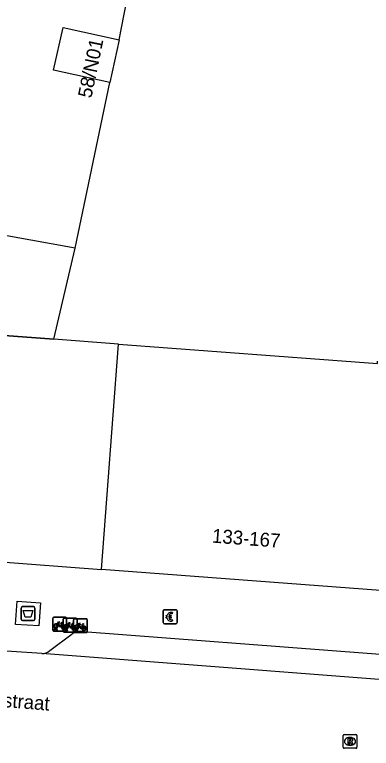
# Model space of a CAD drawing. Extents: x 160861 to 161308, y 384024 to 384878.
# Drawn here: x 161140.4 to 161166, y 384029.8 to 384082.5 of the extents above; entities that cross this region are included whole.
import ezdxf

# ---------------------------------------------------------------- set-up
doc = ezdxf.new("R2010")
doc.units = 0
for name, color, linetype in [('IMGEO_Afval_apart_plaats', 7, 'Continuous'), ('IMGEO_Betaalautomaat', 7, 'Continuous'), ('IMGEO_Fietsenrek', 7, 'Continuous'), ('IMGEO_Openbare_ruimte_label', 7, 'Continuous'), ('IMGEO_Pand', 7, 'Continuous'), ('IMGEO_Pand_nummerreeks', 7, 'Continuous'), ('IMGEO_Pand_overbouw', 7, 'Continuous'), ('IMGEO_Parkeervlak_open', 7, 'Continuous'), ('IMGEO_Rijbaan_lokaal_open', 7, 'Continuous'), ('IMGEO_Rioolput', 7, 'Continuous'), ('IMGEO_Voetpad_gesloten', 7, 'Continuous'), ('IMGEO_Voetpad_open', 7, 'Continuous')]:
    doc.layers.add(name, color=color, linetype=linetype)

msp = doc.modelspace()

# ---------------------------------------------------------------- linework, layer by layer
at = {"layer": 'IMGEO_Afval_apart_plaats'}
for p, q in [((161140.846, 384039.089), (161140.846, 384039.889)), ((161140.846, 384039.889), (161140.846, 384039.089)), ((161140.946, 384039.989), (161141.736, 384039.989)), ((161141.736, 384039.989), (161140.946, 384039.989)), ((161141.836, 384039.889), (161141.836, 384039.089)), ((161141.836, 384039.089), (161141.836, 384039.889)), ((161141.736, 384038.989), (161140.946, 384038.989)), ((161140.946, 384038.989), (161141.736, 384038.989))]:
    msp.add_line(p, q, dxfattribs=at)
msp.add_lwpolyline([(161140.989, 384039.703), (161141.693, 384039.703), (161141.544, 384039.233), (161141.138, 384039.233), (161140.989, 384039.703)], dxfattribs=at)
for centre, start, end in [((161140.946, 384039.889), 90, 180), ((161140.946, 384039.889), 90, 180), ((161141.736, 384039.889), 0, 90), ((161141.736, 384039.889), 360, 90), ((161140.946, 384039.089), 180, 270), ((161140.946, 384039.089), 180, 270), ((161141.736, 384039.089), 270, 0), ((161141.736, 384039.089), 270, 0)]:
    msp.add_arc(centre, 0.1, start, end, dxfattribs=at)
at = {"layer": 'IMGEO_Betaalautomaat'}
for p, q in [((161151.058, 384038.837), (161151.058, 384039.678)), ((161151.058, 384039.678), (161151.058, 384038.837)), ((161151.133, 384039.761), (161151.974, 384039.761)), ((161151.974, 384039.761), (161151.133, 384039.761)), ((161151.72, 384039.566), (161151.703, 384039.466)), ((161152.057, 384039.687), (161152.057, 384038.846)), ((161152.057, 384038.846), (161152.057, 384039.687)), ((161151.341, 384039.225), (161151.341, 384039.293)), ((161151.462, 384039.293), (161151.462, 384039.225)), ((161151.707, 384039.06), (161151.729, 384038.973)), ((161151.983, 384038.762), (161151.142, 384038.762)), ((161151.142, 384038.762), (161151.983, 384038.762))]:
    msp.add_line(p, q, dxfattribs=at)
for points in [[(161151.341, 384039.293), (161151.272, 384039.293), (161151.272, 384039.362), (161151.351, 384039.362)], [(161151.473, 384039.362), (161151.62, 384039.362), (161151.62, 384039.293), (161151.462, 384039.293)], [(161151.346, 384039.156), (161151.272, 384039.156), (161151.272, 384039.225), (161151.341, 384039.225)], [(161151.462, 384039.225), (161151.62, 384039.225), (161151.62, 384039.156), (161151.476, 384039.156)]]:
    msp.add_lwpolyline(points, dxfattribs=at)
for centre, radius, start, end in [((161151.136, 384039.684), 0.0779, 92.4484, 184.2845), ((161151.136, 384039.684), 0.0779, 92.4484, 184.2845), ((161151.634, 384039.286), 0.293, 73.014, 165.0139), ((161151.64, 384039.299), 0.179, 69.3236, 159.5683), ((161151.98, 384039.684), 0.0779, 2.4484, 94.2845), ((161151.98, 384039.684), 0.0779, 2.4484, 94.2845), ((161151.136, 384038.84), 0.0779, 182.4484, 274.2845), ((161151.136, 384038.84), 0.0779, 182.4484, 274.2845), ((161151.607, 384039.211), 0.267, 191.8096, 297.0389), ((161151.64, 384039.226), 0.179, 202.7625, 291.8693), ((161151.98, 384038.84), 0.0779, 272.4484, 4.2845), ((161151.98, 384038.84), 0.0779, 272.4484, 4.2845)]:
    msp.add_arc(centre, radius, start, end, dxfattribs=at)
at = {"layer": 'IMGEO_Fietsenrek'}
for p, q in [((161143.116, 384038.295), (161143.116, 384039.136)), ((161143.116, 384039.136), (161143.116, 384038.295)), ((161143.191, 384039.22), (161144.032, 384039.22)), ((161144.032, 384039.22), (161143.191, 384039.22)), ((161143.863, 384038.236), (161143.863, 384039.077)), ((161143.863, 384039.077), (161143.863, 384038.236)), ((161143.938, 384039.161), (161144.779, 384039.161)), ((161144.779, 384039.161), (161143.938, 384039.161)), ((161144.116, 384039.145), (161144.116, 384038.304)), ((161144.116, 384038.304), (161144.116, 384039.145)), ((161144.602, 384038.197), (161144.602, 384039.038)), ((161144.602, 384039.038), (161144.602, 384038.197)), ((161144.677, 384039.122), (161145.518, 384039.122)), ((161145.518, 384039.122), (161144.677, 384039.122)), ((161144.863, 384039.086), (161144.863, 384038.245)), ((161144.863, 384038.245), (161144.863, 384039.086)), ((161145.602, 384039.047), (161145.602, 384038.206)), ((161145.602, 384038.206), (161145.602, 384039.047)), ((161143.243, 384038.304), (161143.282, 384038.464)), ((161143.277, 384038.304), (161143.243, 384038.304)), ((161143.312, 384038.452), (161143.277, 384038.304)), ((161143.354, 384038.476), (161143.353, 384038.48)), ((161143.395, 384038.304), (161143.361, 384038.446)), ((161143.385, 384038.487), (161143.386, 384038.48)), ((161143.393, 384038.45), (161143.428, 384038.304)), ((161143.428, 384038.304), (161143.395, 384038.304)), ((161143.803, 384038.769), (161143.839, 384038.674)), ((161143.99, 384038.245), (161144.029, 384038.405)), ((161144.059, 384038.393), (161144.024, 384038.245)), ((161144.101, 384038.417), (161144.1, 384038.421)), ((161144.142, 384038.245), (161144.108, 384038.387)), ((161144.132, 384038.428), (161144.133, 384038.421)), ((161144.14, 384038.391), (161144.175, 384038.245)), ((161144.55, 384038.71), (161144.586, 384038.615)), ((161144.729, 384038.206), (161144.768, 384038.366)), ((161144.798, 384038.354), (161144.763, 384038.206)), ((161144.84, 384038.378), (161144.839, 384038.382)), ((161144.881, 384038.206), (161144.847, 384038.348)), ((161144.871, 384038.389), (161144.872, 384038.382)), ((161144.879, 384038.352), (161144.914, 384038.206)), ((161145.289, 384038.671), (161145.325, 384038.576)), ((161144.041, 384038.22), (161143.2, 384038.22)), ((161143.2, 384038.22), (161144.041, 384038.22)), ((161144.788, 384038.161), (161143.947, 384038.161)), ((161143.947, 384038.161), (161144.788, 384038.161)), ((161144.024, 384038.245), (161143.99, 384038.245)), ((161144.175, 384038.245), (161144.142, 384038.245)), ((161145.527, 384038.122), (161144.686, 384038.122)), ((161144.686, 384038.122), (161145.527, 384038.122)), ((161144.763, 384038.206), (161144.729, 384038.206)), ((161144.914, 384038.206), (161144.881, 384038.206))]:
    msp.add_line(p, q, dxfattribs=at)
for points in [[(161143.429, 384038.746), (161143.524, 384038.91), (161143.61, 384038.896), (161143.612, 384038.887), (161143.556, 384038.876), (161143.529, 384038.831), (161143.785, 384038.79)], [(161143.772, 384038.765), (161143.515, 384038.806), (161143.498, 384038.777), (161143.665, 384038.557), (161143.772, 384038.765)], [(161143.785, 384038.79), (161143.81, 384038.839), (161143.804, 384038.843), (161143.781, 384038.847), (161143.769, 384038.854), (161143.768, 384038.857), (161143.77, 384038.862), (161143.865, 384038.847), (161143.867, 384038.837), (161143.857, 384038.824), (161143.845, 384038.818), (161143.831, 384038.824), (161143.803, 384038.769)], [(161144.176, 384038.687), (161144.271, 384038.851), (161144.357, 384038.837), (161144.359, 384038.828), (161144.303, 384038.817), (161144.276, 384038.772), (161144.532, 384038.731)], [(161144.532, 384038.731), (161144.557, 384038.78), (161144.551, 384038.784), (161144.528, 384038.788), (161144.516, 384038.795), (161144.515, 384038.798), (161144.517, 384038.803), (161144.612, 384038.788), (161144.614, 384038.778), (161144.604, 384038.765), (161144.592, 384038.759), (161144.578, 384038.765), (161144.55, 384038.71)], [(161144.915, 384038.648), (161145.01, 384038.812), (161145.096, 384038.798), (161145.098, 384038.789), (161145.042, 384038.778), (161145.015, 384038.733), (161145.271, 384038.692)], [(161143.45, 384038.694), (161143.398, 384038.604), (161143.358, 384038.579), (161143.359, 384038.626), (161143.414, 384038.72)], [(161143.725, 384038.502), (161143.675, 384038.502), (161143.484, 384038.753), (161143.465, 384038.721)], [(161143.82, 384038.667), (161143.79, 384038.744), (161143.681, 384038.526), (161143.724, 384038.526)], [(161143.754, 384038.526), (161143.874, 384038.525), (161143.83, 384038.639)], [(161143.85, 384038.646), (161143.905, 384038.501), (161143.755, 384038.501)], [(161144.197, 384038.635), (161144.145, 384038.545), (161144.105, 384038.52), (161144.106, 384038.567), (161144.161, 384038.661)], [(161144.472, 384038.443), (161144.422, 384038.443), (161144.231, 384038.694), (161144.212, 384038.662)], [(161144.519, 384038.706), (161144.262, 384038.747), (161144.245, 384038.718), (161144.412, 384038.498), (161144.519, 384038.706)], [(161144.567, 384038.608), (161144.537, 384038.685), (161144.428, 384038.467), (161144.471, 384038.467)], [(161144.501, 384038.467), (161144.621, 384038.466), (161144.577, 384038.58)], [(161144.597, 384038.587), (161144.652, 384038.442), (161144.502, 384038.442)], [(161144.936, 384038.596), (161144.884, 384038.506), (161144.844, 384038.481), (161144.845, 384038.528), (161144.9, 384038.622)], [(161145.211, 384038.404), (161145.161, 384038.404), (161144.97, 384038.655), (161144.951, 384038.623)], [(161145.258, 384038.667), (161145.001, 384038.708), (161144.984, 384038.679), (161145.151, 384038.459), (161145.258, 384038.667)], [(161145.306, 384038.569), (161145.276, 384038.646), (161145.167, 384038.428), (161145.21, 384038.428)], [(161145.24, 384038.428), (161145.36, 384038.427), (161145.316, 384038.541)], [(161145.336, 384038.548), (161145.391, 384038.403), (161145.241, 384038.403)], [(161145.271, 384038.692), (161145.296, 384038.741), (161145.29, 384038.745), (161145.267, 384038.749), (161145.255, 384038.756), (161145.254, 384038.759), (161145.256, 384038.764), (161145.351, 384038.749), (161145.353, 384038.739), (161145.343, 384038.726), (161145.331, 384038.72), (161145.317, 384038.726), (161145.289, 384038.671)]]:
    msp.add_lwpolyline(points, dxfattribs=at)
for centre, radius, start, end in [((161143.194, 384039.142), 0.0779, 92.4484, 184.2845), ((161143.194, 384039.142), 0.0779, 92.4484, 184.2845), ((161143.941, 384039.083), 0.0779, 92.4484, 184.2845), ((161143.941, 384039.083), 0.0779, 92.4484, 184.2845), ((161144.038, 384039.142), 0.0779, 2.4484, 94.2845), ((161144.038, 384039.142), 0.0779, 2.4484, 94.2845), ((161144.68, 384039.044), 0.0779, 92.4484, 184.2845), ((161144.68, 384039.044), 0.0779, 92.4484, 184.2845), ((161144.785, 384039.083), 0.0779, 2.4484, 94.2845), ((161144.785, 384039.083), 0.0779, 2.4484, 94.2845), ((161145.524, 384039.044), 0.0779, 2.4484, 94.2845), ((161145.524, 384039.044), 0.0779, 2.4484, 94.2845), ((161143.194, 384038.298), 0.0779, 182.4484, 274.2845), ((161143.194, 384038.298), 0.0779, 182.4484, 274.2845), ((161143.356, 384038.605), 0.159, 62.6766, 242.1369), ((161143.356, 384038.605), 0.129, 63.3192, 238.903), ((161143.336, 384038.476), 0.0499, 12.8025, 158.6934), ((161143.356, 384038.605), 0.159, 253.9967, 271.7867), ((161143.336, 384038.476), 0.0174, 12.8025, 163.4502), ((161143.356, 384038.605), 0.129, 253.415, 269.0204), ((161143.356, 384038.605), 0.129, 283.6043, 43.4302), ((161143.356, 384038.605), 0.159, 283.5766, 46.6042), ((161143.883, 384038.521), 0.159, 113.3408, 178.3217), ((161143.883, 384038.521), 0.159, 187.0065, 105.7708), ((161143.883, 384038.521), 0.129, 113.923, 177.9556), ((161143.883, 384038.521), 0.129, 188.6715, 104.5883), ((161144.103, 384038.546), 0.159, 62.6766, 242.1369), ((161144.103, 384038.546), 0.129, 63.3192, 238.903), ((161144.083, 384038.417), 0.0499, 12.8025, 158.6934), ((161144.038, 384038.298), 0.0779, 272.4484, 4.2845), ((161144.038, 384038.298), 0.0779, 272.4484, 4.2845), ((161144.103, 384038.546), 0.159, 253.9967, 271.7867), ((161144.083, 384038.417), 0.0174, 12.8025, 163.4502), ((161144.103, 384038.546), 0.129, 253.415, 269.0204), ((161144.103, 384038.546), 0.129, 283.6043, 43.4302), ((161144.103, 384038.546), 0.159, 283.5766, 46.6042), ((161144.63, 384038.462), 0.159, 113.3408, 178.3217), ((161144.63, 384038.462), 0.159, 187.0065, 105.7708), ((161144.63, 384038.462), 0.129, 113.923, 177.9556), ((161144.63, 384038.462), 0.129, 188.6715, 104.5883), ((161144.842, 384038.507), 0.159, 62.6766, 242.1369), ((161144.842, 384038.507), 0.129, 63.3192, 238.903), ((161144.822, 384038.378), 0.0499, 12.8025, 158.6934), ((161144.842, 384038.507), 0.159, 253.9967, 271.7867), ((161144.822, 384038.378), 0.0174, 12.8025, 163.4502), ((161144.842, 384038.507), 0.129, 253.415, 269.0204), ((161144.842, 384038.507), 0.129, 283.6043, 43.4302), ((161144.842, 384038.507), 0.159, 283.5766, 46.6042), ((161145.369, 384038.423), 0.159, 113.3408, 178.3217), ((161145.369, 384038.423), 0.159, 187.0065, 105.7708), ((161145.369, 384038.423), 0.129, 113.923, 177.9556), ((161145.369, 384038.423), 0.129, 188.6715, 104.5883), ((161143.941, 384038.239), 0.0779, 182.4484, 274.2845), ((161143.941, 384038.239), 0.0779, 182.4484, 274.2845), ((161144.68, 384038.2), 0.0779, 182.4484, 274.2845), ((161144.68, 384038.2), 0.0779, 182.4484, 274.2845), ((161144.785, 384038.239), 0.0779, 272.4484, 4.2845), ((161144.785, 384038.239), 0.0779, 272.4484, 4.2845), ((161145.524, 384038.2), 0.0779, 272.4484, 4.2845), ((161145.524, 384038.2), 0.0779, 272.4484, 4.2845)]:
    msp.add_arc(centre, radius, start, end, dxfattribs=at)
at = {"layer": 'IMGEO_Pand'}
for points in [[(161147.216, 384077.653), (161143.183, 384078.54), (161143.858, 384081.612), (161147.892, 384080.725)], [(161147.892, 384080.725), (161147.216, 384077.653)], [(161143.21, 384059.211), (161137.041, 384059.677)], [(161147.836, 384058.861), (161143.21, 384059.211)], [(161146.612, 384042.661), (161147.836, 384058.861)], [(161147.836, 384058.861), (161166.449, 384057.454), (161166.463, 384057.634)], [(161131.212, 384043.825), (161146.612, 384042.661)], [(161168.895, 384040.977), (161146.612, 384042.661)]]:
    msp.add_lwpolyline(points, dxfattribs=at)
at = {"layer": 'IMGEO_Pand_overbouw'}
msp.add_lwpolyline([(161139.812, 384066.642), (161137.441, 384067.075), (161136.992, 384064.616), (161137.408, 384064.54), (161137.041, 384059.677), (161143.21, 384059.211), (161144.73, 384065.745)], close=True, dxfattribs=at)
at = {"layer": 'IMGEO_Parkeervlak_open'}
for points in [[(161147.892, 384080.725), (161153.927, 384111.756)], [(161143.21, 384059.211), (161144.73, 384065.745), (161147.216, 384077.653)]]:
    msp.add_lwpolyline(points, dxfattribs=at)
at = {"layer": 'IMGEO_Rijbaan_lokaal_open'}
for points in [[(161142.332, 384036.619), (161137.944, 384036.915)], [(161185.505, 384033.288), (161142.332, 384036.619)]]:
    msp.add_lwpolyline(points, dxfattribs=at)
at = {"layer": 'IMGEO_Rioolput'}
for p, q in [((161163.976, 384029.878), (161163.976, 384030.73)), ((161164.051, 384030.804), (161164.903, 384030.804)), ((161164.464, 384030.584), (161164.489, 384030.584)), ((161164.977, 384030.73), (161164.977, 384029.878)), ((161164.487, 384030.024), (161164.462, 384030.024)), ((161164.903, 384029.804), (161164.051, 384029.804))]:
    msp.add_line(p, q, dxfattribs=at)
for points in [[(161163.976, 384029.878), (161163.976, 384030.73)], [(161164.051, 384030.804), (161164.903, 384030.804)], [(161164.565, 384030.502), (161164.313, 384030.504), (161164.313, 384030.104)], [(161164.491, 384030.423), (161164.437, 384030.423), (161164.437, 384030.342)], [(161164.437, 384030.342), (161164.489, 384030.342)], [(161164.977, 384030.73), (161164.977, 384029.878)], [(161164.313, 384030.104), (161164.437, 384030.104), (161164.437, 384030.266), (161164.448, 384030.266)], [(161164.495, 384030.237), (161164.566, 384030.104), (161164.706, 384030.104), (161164.641, 384030.23)], [(161164.903, 384029.804), (161164.051, 384029.804)]]:
    msp.add_lwpolyline(points, dxfattribs=at)
for centre, radius, start, end in [((161164.053, 384030.728), 0.0765, 91.552, 178.448), ((161164.053, 384030.728), 0.0765, 91.552, 178.448), ((161164.473, 384030.531), 0.19, 274.7715, 282.9687), ((161164.497, 384030.327), 0.0964, 77.0061, 93.1865), ((161164.511, 384030.384), 0.0378, 276.6634, 79.6772), ((161164.564, 384030.392), 0.109, 350.3612, 89.416), ((161164.562, 384030.392), 0.112, 277.5842, 350.9817), ((161164.901, 384030.728), 0.0765, 1.552, 88.448), ((161164.901, 384030.728), 0.0765, 1.552, 88.448), ((161164.053, 384029.88), 0.0765, 181.552, 268.448), ((161164.053, 384029.88), 0.0765, 181.552, 268.448), ((161164.447, 384030.213), 0.0533, 26.0293, 88.6989), ((161164.546, 384030.177), 0.108, 29.5134, 73.7905), ((161164.901, 384029.88), 0.0765, 271.552, 358.448), ((161164.901, 384029.88), 0.0765, 271.552, 358.448)]:
    msp.add_arc(centre, radius, start, end, dxfattribs=at)
for centre, major_axis, ratio, start_param, end_param in [((161164.463, 384030.304), (-0.387, 0.002), 0.722429, 4.712389, 7.853982), ((161164.488, 384030.304), (-0.39, 0.002), 0.717154, 1.570796, 4.712389)]:
    msp.add_ellipse(centre, major_axis=major_axis, ratio=ratio, start_param=start_param, end_param=end_param, dxfattribs=at)
at = {"layer": 'IMGEO_Voetpad_gesloten'}
msp.add_lwpolyline([(161142.234, 384040.262), (161142.125, 384038.606), (161140.447, 384038.716), (161140.556, 384040.372), (161142.234, 384040.262)], dxfattribs=at)
at = {"layer": 'IMGEO_Voetpad_open'}
for points in [[(161142.918, 384036.846), (161144.514, 384038.032)], [(161145.301, 384038.212), (161183.288, 384035.291)]]:
    msp.add_lwpolyline(points, dxfattribs=at)
for centre, radius, start, end in [((161145.173, 384036.962), 1.257, 84.1462, 121.6197), ((161142.38, 384037.366), 0.748, 266.3434, 316.0066)]:
    msp.add_arc(centre, radius, start, end, dxfattribs=at)

# ---------------------------------------------------------------- texts
at = {"layer": 'IMGEO_Openbare_ruimte_label'}
msp.add_text('Pastoor Petersstraat', height=1, rotation=355.4695, dxfattribs=at).set_placement((161130.704, 384033.475))
at = {"layer": 'IMGEO_Pand_nummerreeks'}
for s, rotation, p in [('58/N01', 78.3106, (161145.893, 384076.492)), ('133-167', 355.6417, (161154.539, 384044.594))]:
    msp.add_text(s, height=1, rotation=rotation, dxfattribs=at).set_placement(p)

doc.saveas('drawing.dxf')
